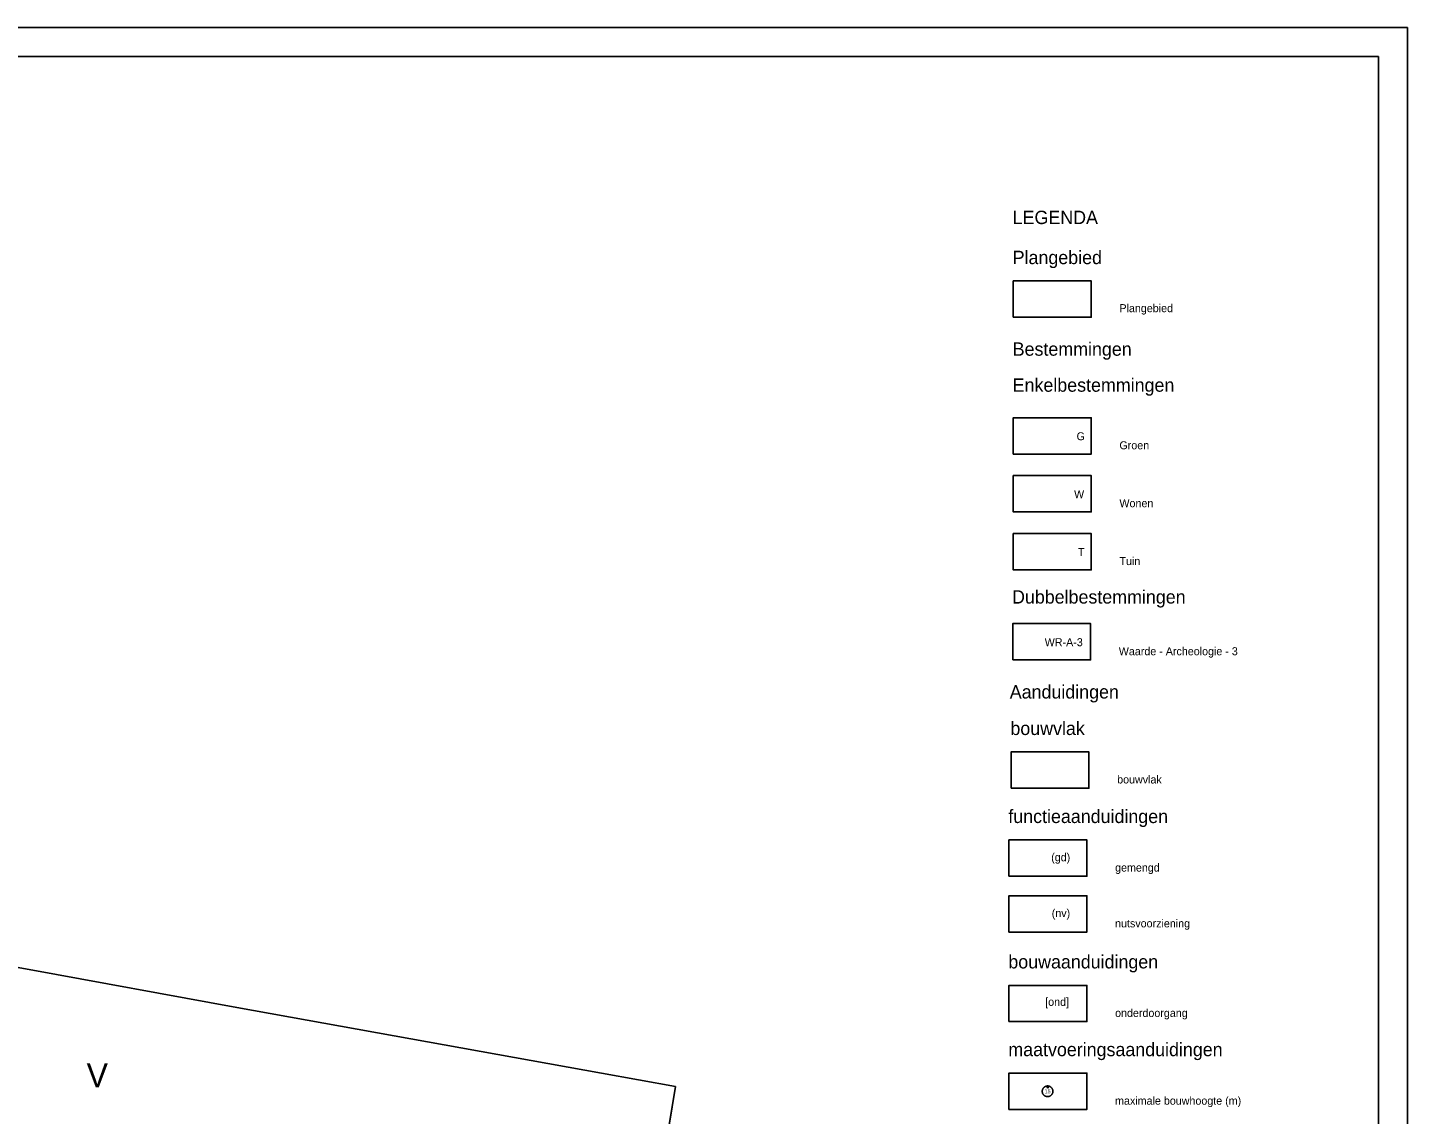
# Model space of a CAD drawing. Extents: x 104705 to 105186, y 424858 to 425816.
# Drawn here: x 104992.1 to 105186, y 425045.2 to 425198 of the extents above; entities that cross this region are included whole.
import ezdxf

# ---------------------------------------------------------------- set-up
doc = ezdxf.new("R2010")
doc.units = 0
for name, color, linetype in [('BP_ALG_bestemminggrens', 7, 'Continuous'), ('BP_ALG_kader', 7, 'Continuous'), ('BP_BA_onderdoorgang', 7, 'Continuous'), ('BP_BPG_Plangebied', 7, 'Continuous'), ('BP_BV_Bouwvlak', 7, 'Continuous'), ('BP_DB_Waarde - Archeologie - 3', 7, 'Continuous'), ('BP_EB_Groen', 7, 'Continuous'), ('BP_EB_Tuin', 7, 'Continuous'), ('BP_EB_Verkeer', 7, 'Continuous'), ('BP_EB_Wonen', 7, 'Continuous'), ('BP_FA_gemengd', 7, 'Continuous'), ('BP_MS_s104_maximale bouwhoogte (m)', 7, 'Continuous'), ('BP_MV_maatvoering', 7, 'Continuous'), ('BP_TXT_tekst', 7, 'Continuous')]:
    doc.layers.add(name, color=color, linetype=linetype)

msp = doc.modelspace()

# ---------------------------------------------------------------- linework, layer by layer
at = {"layer": 'BP_ALG_bestemminggrens'}
for points in [[(105130.62, 425138.03), (105141.56, 425138.03), (105141.56, 425143.13), (105130.62, 425143.13)], [(105130.62, 425129.9), (105141.56, 425129.9), (105141.56, 425135), (105130.62, 425135)], [(105130.62, 425121.76), (105141.56, 425121.76), (105141.56, 425126.86), (105130.62, 425126.86)], [(105130.53, 425109.1), (105141.48, 425109.1), (105141.48, 425114.2), (105130.53, 425114.2)]]:
    msp.add_lwpolyline(points, close=True, dxfattribs=at)
at = {"layer": 'BP_ALG_kader'}
for p, q in [((104704.86, 425197.96), (105186, 425197.96)), ((105186, 425197.96), (105186, 424857.76)), ((105181.95, 425193.91), (104708.91, 425193.91)), ((105181.95, 424861.81), (105181.95, 425193.91))]:
    msp.add_line(p, q, dxfattribs=at)
at = {"layer": 'BP_BA_onderdoorgang'}
msp.add_lwpolyline([(105130.01, 425058.27), (105140.96, 425058.27), (105140.96, 425063.37), (105130.01, 425063.37)], close=True, dxfattribs=at)
at = {"layer": 'BP_BPG_Plangebied'}
msp.add_lwpolyline([(105130.62, 425157.25), (105141.56, 425157.25), (105141.56, 425162.35), (105130.62, 425162.35)], close=True, dxfattribs=at)
for points in [[(104878.61, 425085.97), (104884.92, 425084.96), (104929.1, 425077.02), (104992.29, 425065.59), (105021.48, 425060.27), (105072.73, 425051.04), (105083.13, 425049.14)], [(105076.34, 425008.23), (105076.61, 425009.22), (105077.58, 425015.43), (105083.13, 425049.14)]]:
    msp.add_lwpolyline(points, dxfattribs=at)
at = {"layer": 'BP_BV_Bouwvlak'}
msp.add_lwpolyline([(105130.3, 425091.07), (105141.25, 425091.07), (105141.25, 425096.18), (105130.3, 425096.18)], close=True, dxfattribs=at)
at = {"layer": 'BP_DB_Waarde - Archeologie - 3'}
for points in [[(105130.53, 425109.1), (105141.48, 425109.1), (105141.48, 425114.2), (105130.53, 425114.2), (105130.53, 425109.1)], [(105083.13, 425049.14), (105072.73, 425051.04), (105021.48, 425060.27), (104992.29, 425065.59), (104929.1, 425077.02), (104884.92, 425084.96), (104878.61, 425085.97)], [(105076.34, 425008.23), (105076.61, 425009.22), (105077.58, 425015.43), (105083.13, 425049.14)]]:
    msp.add_lwpolyline(points, dxfattribs=at)
at = {"layer": 'BP_EB_Groen'}
msp.add_lwpolyline([(105130.62, 425143.13), (105130.62, 425138.03), (105141.56, 425138.03), (105141.56, 425143.13), (105130.62, 425143.13)], dxfattribs=at)
at = {"layer": 'BP_EB_Tuin'}
msp.add_lwpolyline([(105130.62, 425126.86), (105130.62, 425121.76), (105141.56, 425121.76), (105141.56, 425126.86), (105130.62, 425126.86)], dxfattribs=at)
at = {"layer": 'BP_EB_Verkeer'}
msp.add_line((105081.42, 425038.74), (105083.13, 425049.14), dxfattribs=at)
msp.add_lwpolyline([(105083.13, 425049.14), (105072.73, 425051.04), (105021.48, 425060.27), (104992.29, 425065.59), (104929.1, 425077.02), (104884.92, 425084.96), (104878.61, 425085.97)], dxfattribs=at)
at = {"layer": 'BP_EB_Wonen'}
msp.add_lwpolyline([(105130.62, 425135), (105130.62, 425129.9), (105141.56, 425129.9), (105141.56, 425135), (105130.62, 425135)], dxfattribs=at)
at = {"layer": 'BP_FA_gemengd'}
for points in [[(105130.01, 425078.7), (105140.96, 425078.7), (105140.96, 425083.8), (105130.01, 425083.8)], [(105130.01, 425070.86), (105140.96, 425070.86), (105140.96, 425075.96), (105130.01, 425075.96)]]:
    msp.add_lwpolyline(points, close=True, dxfattribs=at)
at = {"layer": 'BP_MS_s104_maximale bouwhoogte (m)'}
for points in [[(105136.1, 425048.14), (105136.08, 425048.1), (105136.05, 425048.06), (105136.02, 425048.02), (105135.99, 425047.98), (105135.96, 425047.95), (105135.93, 425047.92), (105135.89, 425047.89), (105135.85, 425047.86), (105135.81, 425047.83), (105135.77, 425047.81), (105135.73, 425047.79), (105135.68, 425047.78), (105135.64, 425047.76), (105135.59, 425047.75), (105135.55, 425047.74), (105135.5, 425047.74), (105135.45, 425047.73), (105135.41, 425047.73), (105135.36, 425047.74), (105135.31, 425047.74), (105135.27, 425047.75), (105135.22, 425047.76), (105135.18, 425047.78), (105135.13, 425047.8), (105135.09, 425047.82), (105135.05, 425047.84), (105135.01, 425047.86), (105134.97, 425047.89), (105134.94, 425047.92), (105134.9, 425047.95), (105134.87, 425047.99), (105134.84, 425048.03), (105134.81, 425048.06), (105134.79, 425048.1), (105134.76, 425048.15), (105134.74, 425048.19), (105134.73, 425048.23), (105134.71, 425048.28), (105134.7, 425048.32), (105134.69, 425048.37), (105134.69, 425048.42), (105134.68, 425048.46), (105134.68, 425048.51), (105134.69, 425048.56), (105134.69, 425048.6), (105134.7, 425048.65), (105134.71, 425048.7), (105134.73, 425048.74), (105134.75, 425048.78), (105134.77, 425048.83), (105134.79, 425048.87), (105134.82, 425048.91), (105134.84, 425048.95), (105134.87, 425048.98), (105134.91, 425049.02), (105134.94, 425049.05), (105134.98, 425049.08), (105135.02, 425049.1), (105135.06, 425049.13), (105135.1, 425049.15), (105135.14, 425049.17), (105135.18, 425049.19), (105135.23, 425049.2), (105135.27, 425049.22), (105135.32, 425049.22), (105135.37, 425049.23), (105135.41, 425049.23), (105135.46, 425049.23), (105135.51, 425049.23), (105135.56, 425049.22), (105135.6, 425049.21), (105135.65, 425049.2), (105135.69, 425049.19), (105135.74, 425049.17), (105135.78, 425049.15), (105135.82, 425049.13), (105135.86, 425049.1), (105135.9, 425049.07), (105135.93, 425049.04), (105135.97, 425049.01), (105136, 425048.98), (105136.03, 425048.94), (105136.06, 425048.9), (105136.08, 425048.86), (105136.1, 425048.82), (105136.12, 425048.78), (105136.14, 425048.73), (105136.16, 425048.69), (105136.17, 425048.64), (105136.18, 425048.6), (105136.18, 425048.55), (105136.18, 425048.5), (105136.18, 425048.45), (105136.18, 425048.41), (105136.17, 425048.36), (105136.17, 425048.32), (105136.15, 425048.27), (105136.14, 425048.22), (105136.12, 425048.18)], [(105135.45, 425048.93), (105135.32, 425049.16), (105135.58, 425049.16)]]:
    msp.add_lwpolyline(points, close=True, dxfattribs=at)
at = {"layer": 'BP_MV_maatvoering'}
msp.add_lwpolyline([(105130.01, 425045.94), (105140.96, 425045.94), (105140.96, 425051.04), (105130.01, 425051.04)], close=True, dxfattribs=at)

# ---------------------------------------------------------------- texts
at = {"layer": 'BP_MS_s104_maximale bouwhoogte (m)'}
msp.add_text('15', height=0.562, dxfattribs=at).set_placement((105135, 425048.2))
at = {"layer": 'BP_TXT_tekst'}
for s, height, p in [('LEGENDA', 1.875, (105130.53, 425170.35)), ('Plangebied', 1.875, (105130.53, 425164.72)), ('Plangebied', 1.125, (105145.53, 425157.97)), ('Bestemmingen', 1.875, (105130.53, 425151.85)), ('Enkelbestemmingen', 1.875, (105130.53, 425146.79)), ('G', 1.12, (105139.51, 425139.97)), ('Groen', 1.125, (105145.53, 425138.7)), ('W', 1.12, (105139.16, 425131.83)), ('Wonen', 1.125, (105145.53, 425130.56)), ('T', 1.12, (105139.7, 425123.7)), ('Tuin', 1.125, (105145.53, 425122.43)), ('Dubbelbestemmingen', 1.875, (105130.44, 425117.02)), ('WR-A-3', 1.125, (105135.03, 425111.03)), ('Waarde - Archeologie - 3', 1.125, (105145.44, 425109.76)), ('Aanduidingen', 1.875, (105130.12, 425103.68)), ('bouwvlak', 1.875, (105130.21, 425098.55)), ('bouwvlak', 1.125, (105145.21, 425091.74)), ('functieaanduidingen', 1.875, (105129.92, 425086.18)), ('(gd)', 1.125, (105135.94, 425080.81)), ('gemengd', 1.125, (105144.92, 425079.36)), ('(nv)', 1.125, (105136.02, 425072.96)), ('nutsvoorziening', 1.125, (105144.92, 425071.52)), ('bouwaanduidingen', 1.875, (105129.92, 425065.75)), ('[ond]', 1.125, (105135.1, 425060.49)), ('onderdoorgang', 1.125, (105144.92, 425058.93)), ('maatvoeringsaanduidingen', 1.875, (105129.92, 425053.42)), ('V', 3.38, (105000.38, 425049.05)), ('maximale bouwhoogte (m)', 1.125, (105144.92, 425046.6))]:
    msp.add_text(s, height=height, dxfattribs=at).set_placement(p)

doc.saveas('drawing.dxf')
